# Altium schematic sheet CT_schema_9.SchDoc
size 278 x 170 mm
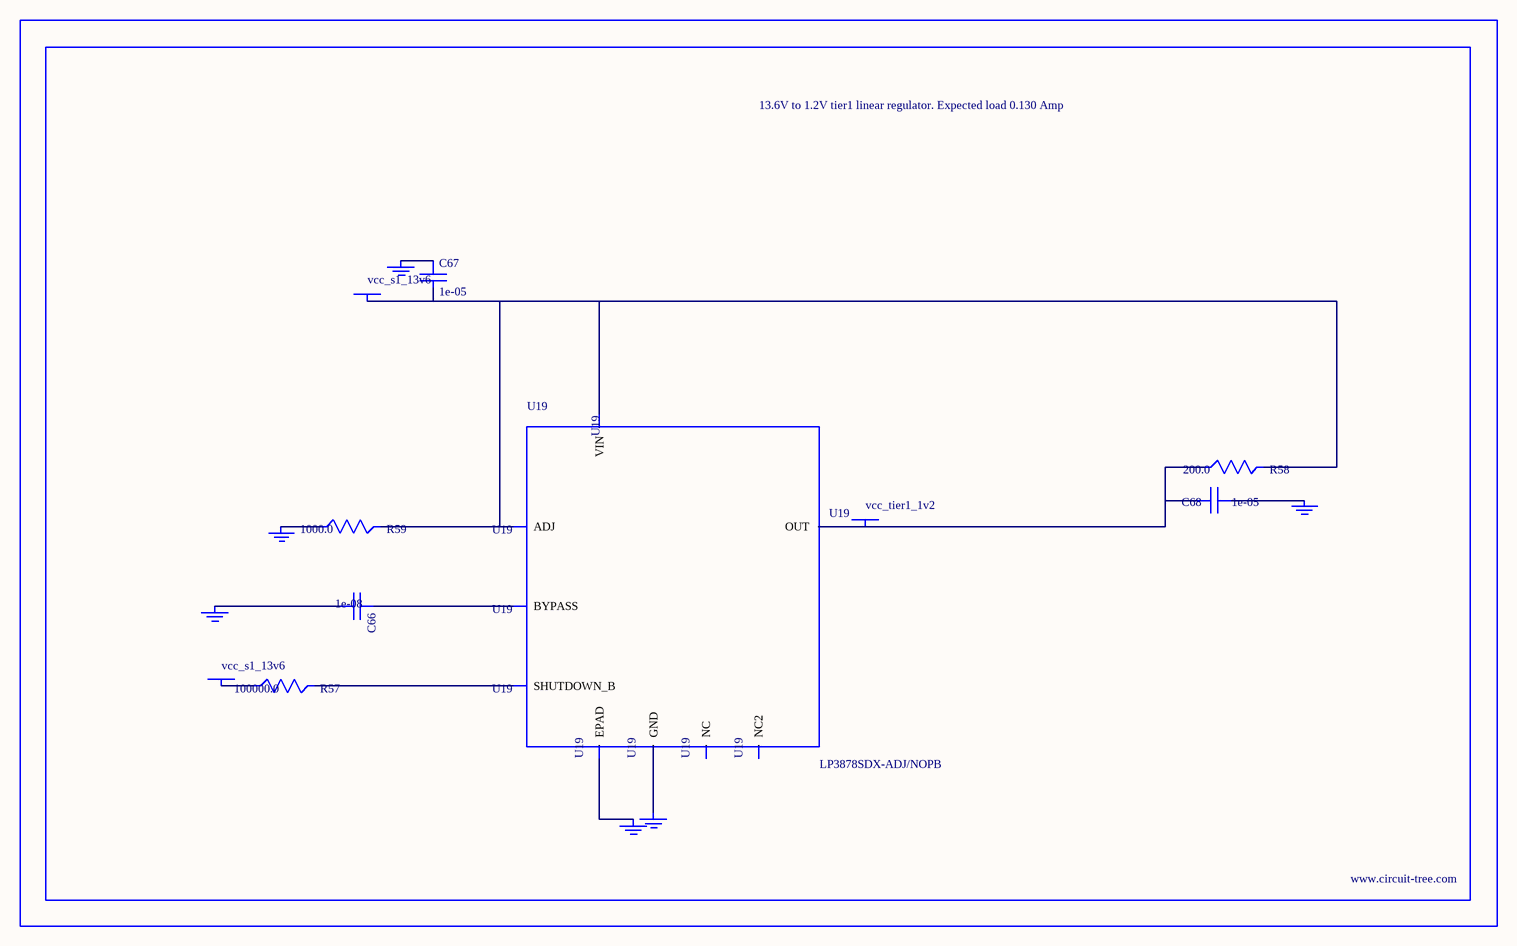
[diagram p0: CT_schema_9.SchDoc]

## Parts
BORDER8  (no value)
C66  1e-08  [C0402]
C67  1e-05  [C1210]
C68  1e-05  [C0805]
GND_INSTANCE_8_0  (no value)
GND_INSTANCE_8_1  (no value)
GND_INSTANCE_8_2  (no value)
GND_INSTANCE_8_3  (no value)
GND_INSTANCE_8_4  (no value)
GND_INSTANCE_8_5  (no value)
POWER_INSTANCE_8_0  vcc_s1_13v6
POWER_INSTANCE_8_1  vcc_s1_13v6
POWER_INSTANCE_8_2  vcc_tier1_1v2
R57  100000.0  [R0603]
R58  200.0  [R0603]
R59  1000.0  [R0603]
U19  LP3878SDX-ADJ/NOPB  [WSON-8]

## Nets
NetC66_1: C66.1 U19.1(BYPASS)
NetC66_2: C66.2 GND_INSTANCE_8_0.0(GND)
NetC67_1: C67.1 GND_INSTANCE_8_1.0(GND)
NetC67_2: C67.2 POWER_INSTANCE_8_0.0(PWR) R58.2 R59.2 U19.4(VIN) U19.6(ADJ)
NetC68_1: C68.1 GND_INSTANCE_8_2.0(GND)
NetC68_2: C68.2 POWER_INSTANCE_8_2.0(PWR) R58.1 U19.5(OUT)
NetGND_INSTANCE_8_3_0: GND_INSTANCE_8_3.0(GND) R59.1
NetGND_INSTANCE_8_4_0: GND_INSTANCE_8_4.0(GND) U19.PAD(EPAD)
NetGND_INSTANCE_8_5_0: GND_INSTANCE_8_5.0(GND) U19.3(GND)
NetPOWER_INSTANCE_8_1_0: POWER_INSTANCE_8_1.0(PWR) R57.1
NetR57_2: R57.2 U19.8(SHUTDOWN_B)

Not connected (* = marked no-connect by the designer): U19 2(NC) 7(NC2)

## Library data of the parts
BORDER8 = BORDER_PAGE8
C66 = C0402C103K3RAC
C67 = C1210C106K5PACTU
C68 = GRM219R60J106ME19D
GND_INSTANCE_8_0-GND_INSTANCE_8_5 = GND
POWER_INSTANCE_8_0-POWER_INSTANCE_8_2 = PWR
R57 = RC0603JR-07100KL
R58 = RC0603JR-07200RL
R59 = RC0603JR-071KL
